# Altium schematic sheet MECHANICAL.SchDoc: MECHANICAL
size A4; Date: Not used; ApprovedBy: Not used; CheckedBy: Not used; Author: Not used; CompanyName: STMicroelectronics; DrawnBy: Not used; Engineer: Not used; Organization: Not used; Address1: Not used; Address2: Not used; Address3: Not used; Address4: Not used; DocumentNumber: Not used; Revision: Not used; SheetNumber: 16; SheetTotal: 16
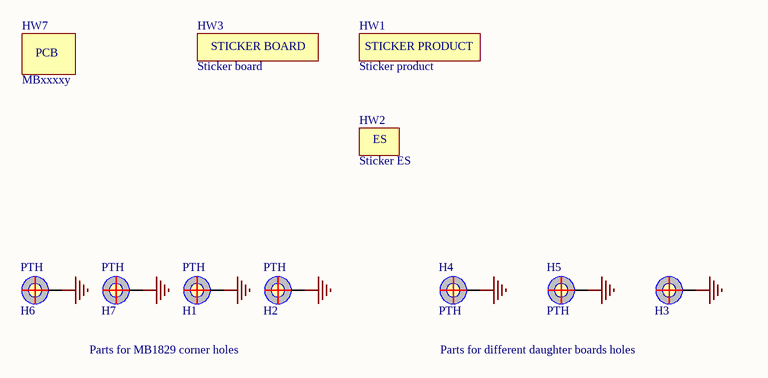
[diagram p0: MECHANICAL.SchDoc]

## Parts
H1  value PTH  [PTH_350_700_H-12]  (hidden comment: POSITION HOLE)  (no BOM)
H2  value PTH  [PTH_350_700_H-12]  (hidden comment: POSITION HOLE)  (no BOM)
H3  POSITION HOLE  [PTH_450_900]  (value not drawn)  (no BOM)
H4  value PTH  [PTH_350_500]  (hidden comment: POSITION HOLE)  (no BOM)
H5  value PTH  [PTH_350_500]  (hidden comment: POSITION HOLE)  (no BOM)
H6  value PTH  [PTH_350_700_H-12]  (hidden comment: POSITION HOLE)  (no BOM)
H7  value PTH  [PTH_350_700_H-12]  (hidden comment: POSITION HOLE)  (no BOM)
HW1  value Sticker product  [STICKER_PRODUCT_25X5]  (hidden comment: STICKER_PRODUCT)  (no BOM)
HW2  value Sticker ES  [STICKER_ES_6X6]  (hidden comment: STICKER_ES)  (no BOM)
HW3  value Sticker board  [STICKER_BOARD_25X9]  (hidden comment: STICKER_BOARD)  (no BOM)
HW7  value MBxxxxy  (hidden comment: PCB)  (no BOM)

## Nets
GND: H1.1 H2.1 H3.1 H4.1 H5.1 H6.1 H7.1

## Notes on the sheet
- Parts for MB1829 corner holes
- Parts for different daughter boards holes

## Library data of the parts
H1 H2 H6 H7 = MCD-02916: Position hole,  C7D3R5 with 12mm M3 pillar on bottom; Part_Type: Misc; Part_Preference: Recommended; ShowFields: YES; ID: 5032
H3 = MCD-01612: POSITION HOLE C9D4R5; Part_Type: Misc; Part_Preference: Recommended; ShowFields: YES; ID: 3712
H4 H5 = MCD-02915: Position Hole C5D3R5: with no pillar in 3D, with pad design = c500h350m510.; Part_Type: Misc; Part_Preference: Recommended; ShowFields: YES; ID: 5031
HW1 = MCD-02189: Sticker product 25x5 mm; Part_Preference: Recommended; Part_Type: Misc
HW2 = MCD-00234: Sticker ES 6x6 mm; Part_Type: Misc; Part_Preference: Recommended
HW3 = MCD-00235: Sticker Board 25x9 mm; Part_Preference: Recommended; Part_Type: Misc
HW7 = MCD-00216: PCB, xxxx for PCB number, Y for PCB revision; Part_Type: Misc; Part_Preference: Forbidden; ShowFields: YES; ID: 2653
